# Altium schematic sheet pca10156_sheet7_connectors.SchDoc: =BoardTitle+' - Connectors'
size A3; Organization: Nordic Semiconductor; DocumentNumber: 7; SheetNumber: 7; SheetTotal: 8; CompanyName: Nordic Semiconductor; DocumentSize: A4
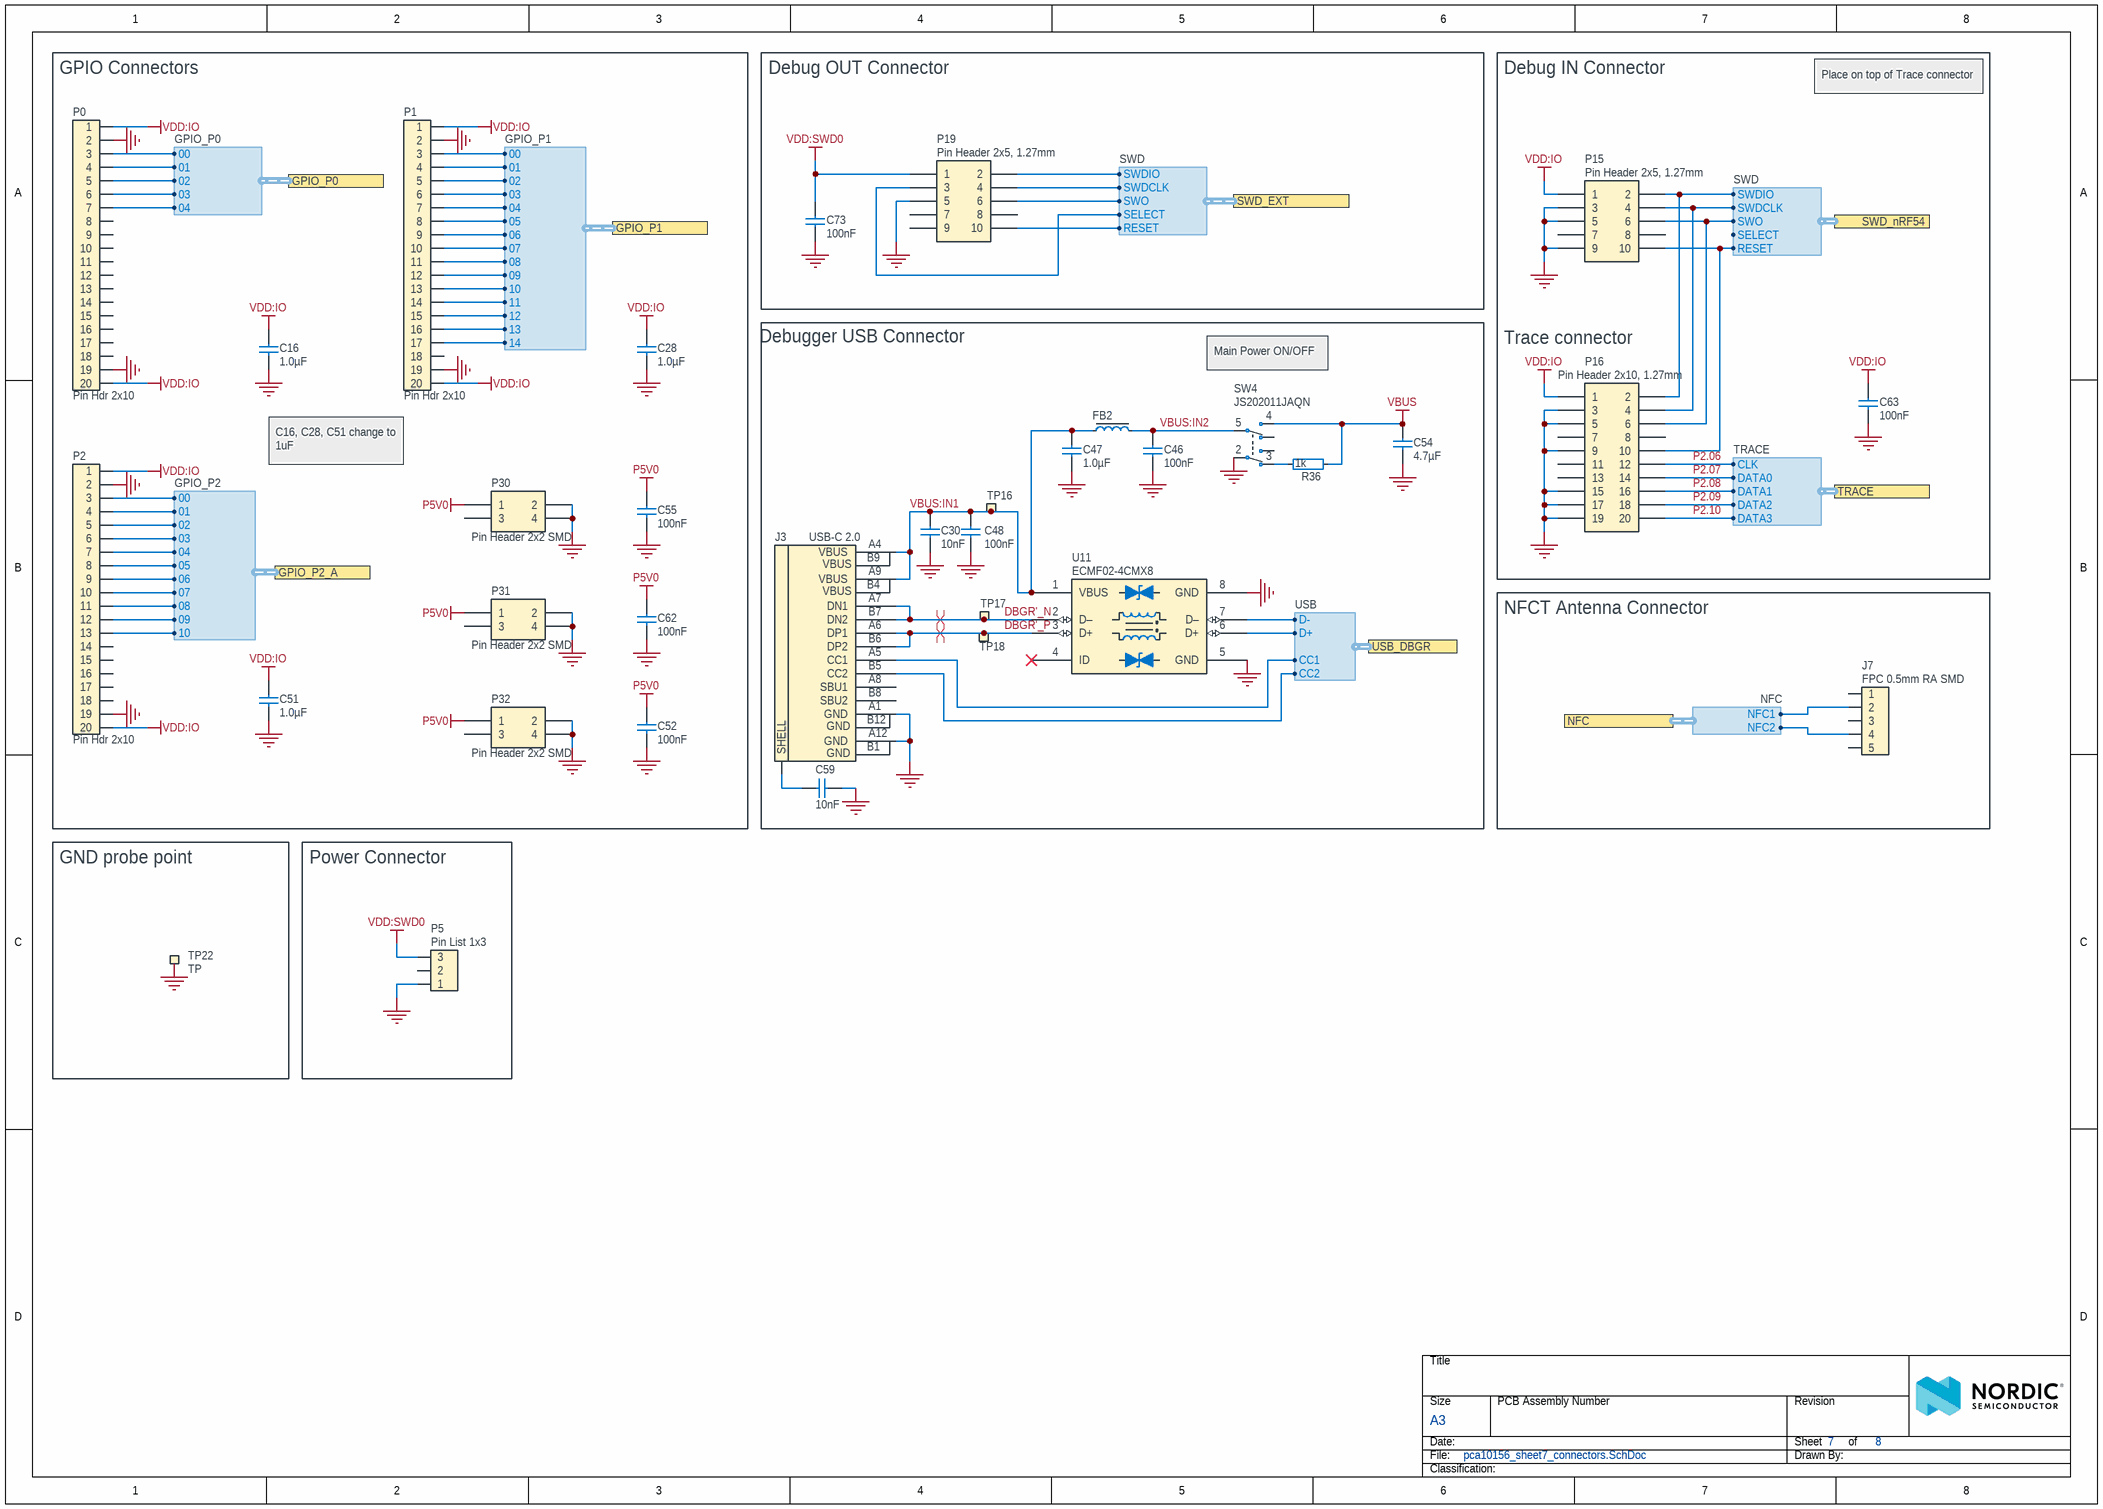
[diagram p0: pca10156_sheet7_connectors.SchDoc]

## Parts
C16  1.0µF  [CAPC1005X04L]
C28  1.0µF  [CAPC1005X04L]
C30  10nF  [CAPC0603X03L_C]
C46  100nF  [CAPC0603X03L_C]
C47  1.0µF  [CAPC1005X04L]
C48  100nF  [CAPC0603X03L_C]
C51  1.0µF  [CAPC1005X04L]
C52  100nF  [CAPC0603X03L_C]
C54  4.7µF  [CAPC1608X06L]
C55  100nF  [CAPC0603X03L_C]
C59  10nF  [CAPC1608X06L]
C62  100nF  [CAPC0603X03L_C]
C63  100nF  [CAPC0603X03L_C]
C73  100nF  [CAPC0603X03L_C]
FB2  120R/0.55A  [INDC1005X04L]  (value not drawn)
J3  USB-C 2.0  [SD-80259-001]
J7  FPC 0.5mm RA SMD  [FPC_05P-0.5mm-RA-SMD]
P0  Pin Hdr 2x10  [HDR_2x10-SMD]
P1  Pin Hdr 2x10  [HDR_2x10-SMD]
P2  Pin Hdr 2x10  [HDR_2x10-SMD]
P5  Pin List 1x3  [LIST_1x3_SMD]
P15  Pin Header 2x5, 1.27mm  [HDR_2x5-SMD-1.27mm-K]
P16  Pin Header 2x10, 1.27mm  [HDR_2x10-SMD-1.27mm-NC]
P19  Pin Header 2x5, 1.27mm  [HDR_2x5-SMD-1.27mm-K]
P30  Pin Header 2x2 SMD  [HDR_2x2-SMD]
P31  Pin Header 2x2 SMD  [HDR_2x2-SMD]
P32  Pin Header 2x2 SMD  [HDR_2x2-SMD]
R36  1k  [RESC0603X03L_C]
SW4  Manufacturer Part Number: JS202011JAQN  [JS102011JAQN]  (hidden comment: Switch)
TP16  Ø1.5mm,SMD  [TP_SMD_D1.5mm]  (value not drawn)  (no BOM)
TP17  Ø1.5mm,SMD  [TP_SMD_D1.5mm]  (value not drawn)  (no BOM)
TP18  Ø1.5mm,SMD  [TP_SMD_D1.5mm]  (value not drawn)  (no BOM)
TP22  TP  [S1751]
U11  ECMF02-4CMX8  [UFDFN50P120X250X55-8N]

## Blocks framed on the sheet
GPIO Connectors: C16 C28 C51 C52 C55 C62 P0-P2 P30-P32
Debug OUT Connector: C73 P19
Debugger USB Connector: C30 C46-C48 C54 C59 FB2 J3 R36 SW4 TP16-TP18 U11
NFCT Antenna Connector: J7
GND probe point: TP22
Power Connector: P5

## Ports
GPIO_P0 (harness GPIO_P0), GPIO_P1 (harness GPIO_P1), GPIO_P2_A (harness GPIO_P2), NFC (harness NFC), SWD_EXT (harness SWD), SWD_nRF54 (harness SWD), TRACE (harness TRACE), USB_DBGR (harness USB)

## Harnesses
USB: D+, D-, CC1, CC2
SWD: SWDIO, SWDCLK, SWO, RESET, SELECT
NFC: NFC2, NFC1
GPIO_P1: 00, 01, 02, 03, 04, 05, 06, 07, 08, 09, 10, 11, 12, 13, 14
GPIO_P2: 00, 01, 02, 03, 04, 05, 06, 07, 08, 09, 10
TRACE: CLK, DATA0, DATA1, DATA3, DATA2
GPIO_P0: 02, 03, 04, 00, 01

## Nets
GND: C16.1 C28.1 C30.2 C46.1 C47.1 C48.1 C51.1 C52.1 C54.2 C55.1 C59.2 C62.1 C63.1 C73.1 J3.A1(GND) J3.A12(GND) P0.2 P0.19 P1.2 P1.19 P2.2 P2.19 P5.1 P15.3 P15.5 P15.9 P16.3 P16.5 P16.9 P16.15 P16.17 P16.19 P19.5 P30.2 P30.4 P31.2 P31.4 P32.2 P32.4 SW4.2(COM-1) TP22.1 U11.5(GND) U11.8(GND)
P5V0: C52.2 C55.2 C62.2 P30.1 P31.1 P32.1
VBUS: C54.1 R36.2 SW4.4(N.O-2)
VDD:IO: C16.2 C28.2 C51.2 C63.2 P0.1 P0.20 P1.1 P1.20 P2.1 P2.20 P15.1 P16.1
VDD:SWD0: C73.2 P5.3 P19.1
DBGR'_N: J3.A7(DN1) J3.B7(DN2) TP17.1 U11.2(D–)
DBGR'_P: J3.A6(DP1) J3.B6(DP2) TP18.1 U11.3(D+)
P2.06: P16.12 ; port TRACE.CLK
P2.07: P16.14 ; port TRACE.DATA0
P2.08: P16.16 ; port TRACE.DATA1
P2.09: P16.18 ; port TRACE.DATA2
P2.10: P16.20 ; port TRACE.DATA3
VBUS:IN1: C30.1 C47.2 C48.2 FB2.1 J3.A4(VBUS) J3.A9(VBUS) TP16.1 U11.1(VBUS)
VBUS:IN2: C46.2 FB2.2 SW4.5(COM-2)
NetC59_1: C59.1 J3.SHLD(SHELL)
NetJ3_A5: J3.A5(CC1) ; port USB_DBGR.CC1
NetJ3_B5: J3.B5(CC2) ; port USB_DBGR.CC2
NetJ7_2: J7.2 ; port NFC.NFC1
NetJ7_4: J7.4 ; port NFC.NFC2
NetP0_3: P0.3 ; port GPIO_P0.00
NetP0_4: P0.4 ; port GPIO_P0.01
NetP0_5: P0.5 ; port GPIO_P0.02
NetP0_6: P0.6 ; port GPIO_P0.03
NetP0_7: P0.7 ; port GPIO_P0.04
NetP1_3: P1.3 ; port GPIO_P1.00
NetP1_4: P1.4 ; port GPIO_P1.01
NetP1_5: P1.5 ; port GPIO_P1.02
NetP1_6: P1.6 ; port GPIO_P1.03
NetP1_7: P1.7 ; port GPIO_P1.04
NetP1_8: P1.8 ; port GPIO_P1.05
NetP1_9: P1.9 ; port GPIO_P1.06
NetP1_10: P1.10 ; port GPIO_P1.07
NetP1_11: P1.11 ; port GPIO_P1.08
NetP1_12: P1.12 ; port GPIO_P1.09
NetP1_13: P1.13 ; port GPIO_P1.10
NetP1_14: P1.14 ; port GPIO_P1.11
NetP1_15: P1.15 ; port GPIO_P1.12
NetP1_16: P1.16 ; port GPIO_P1.13
NetP1_17: P1.17 ; port GPIO_P1.14
NetP2_3: P2.3 ; port GPIO_P2_A.00
NetP2_4: P2.4 ; port GPIO_P2_A.01
NetP2_5: P2.5 ; port GPIO_P2_A.02
NetP2_6: P2.6 ; port GPIO_P2_A.03
NetP2_7: P2.7 ; port GPIO_P2_A.04
NetP2_8: P2.8 ; port GPIO_P2_A.05
NetP2_9: P2.9 ; port GPIO_P2_A.06
NetP2_10: P2.10 ; port GPIO_P2_A.07
NetP2_11: P2.11 ; port GPIO_P2_A.08
NetP2_12: P2.12 ; port GPIO_P2_A.09
NetP2_13: P2.13 ; port GPIO_P2_A.10
NetP15_2: P15.2 P16.2 ; port SWD_nRF54.SWDIO
NetP15_4: P15.4 P16.4 ; port SWD_nRF54.SWDCLK
NetP15_6: P15.6 P16.6 ; port SWD_nRF54.SWO
NetP15_10: P15.10 P16.10 ; port SWD_nRF54.RESET
NetP19_2: P19.2 ; port SWD_EXT.SWDIO
NetP19_3: P19.3 ; port SWD_EXT.SELECT
NetP19_4: P19.4 ; port SWD_EXT.SWDCLK
NetP19_6: P19.6 ; port SWD_EXT.SWO
NetP19_10: P19.10 ; port SWD_EXT.RESET
NetR36_1: R36.1 SW4.3(N.C-1)
NetU11_6: U11.6(D+) ; port USB_DBGR.D+
NetU11_7: U11.7(D–) ; port USB_DBGR.D-

Not connected (* = marked no-connect by the designer): J3 A8(SBU1) B8(SBU2); J7 1 3 5; P0 8 9 10 11 12 13 14 15 16 17 18; P1 18; P2 14 15 16 17 18; P5 2; P15 7 8; P16 7 8 11 13; P19 7 8 9; P30 3; P31 3; P32 3; SW4 1(N.O-1) 6(N.C-2); U11 4(ID)*

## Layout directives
differential pair; differential pair class DBGR; net class DBGR_USB: DBGR'_N, DBGR'_P

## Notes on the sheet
- Debug IN Connector
- Place on top of Trace connector
- Main Power ON/OFF
- (near P16) Trace connector
- C16, C28, C51 change to 1uF

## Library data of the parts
C16 C28 C51 = C0402-1µ0-6.3V-X5R-10%: Capacitor, X5R, ±10%, 6.3V; Manufacturer: N.A.; Part number Norautron: 26207137; Part number NEMS: 100200498; Pad Count: 2; Component Status: Active
C30 = C0201-10n: Capacitor, X7R, ±10%; Manufacturer: N.A.; Part number IPS: 00000003480; Part number Norautron: 26621779; Part number NEMS: 100200067; Note: 10V; Pad Count: 2; Component Status: Active
C46 C48 C52 C55 C62 C63 C73 = C0201-100n: Capacitor, X5R, ±10%; Manufacturer: N.A.; Part number IPS: 00000001248, 00000002505; Part number Norautron: 262071862; Part number NEMS: 100200078; Note: 16V; Pad Count: 2; Component Status: Active
C47 = C0402-1µ0-16V-X5R: Capacitor, Ceramic, X5R, ±10%, 16V; Manufacturer: Murata; Manufacturer Part Number: GRT155R61C105KE01D; Part number NEMS: 100200452; Component Status: Active; Pad Count: 2; Artikkelnr Noca: N.A.
C54 = C0603-4µ7-10V-X7S: Capacitor, X7S, ±10%, 10V; Manufacturer: N.A.; Part number IPS: 00000001779; Part number NEMS: 100200351; Pad Count: 2; Artikkelnr Noca: 20030013; Component Status: Active
C59 = C0603-10n-100V-X7R: Capacitor, X7R, ±10%, 100V; Manufacturer: Murata; Manufacturer Part Number: GCM188R72A103KA37D; Part number NEMS: 100200349; Component Status: Active; Pad Count: 2; Artikkelnr Noca: N.A.
FB2 = FB0402-120R@100M-500mA: Ferrite Bead, 120 Ohm @ 100MHz, 500mA, 250 mOhm Max; Manufacturer: Murata; Manufacturer Part Number: BLM15AG121SN1D; Part number IPS: 00000009954; Part number Norautron: 265230631; Part number NEMS: 100300099; Note: Chip EMIFIL Inductor Type Chip Ferrite Bead; Artikkelnr Noca: 33029317; Pad Count: 2; Component Status: Active
J3 = SD-80259-1021: USB-C Receptacle, 16 Pin, USB 2.0; Manufacturer: Bellweather Electronic Corp.; Part number NEMS: 100500830; Component Status: Active; Pad Count: 16; Note: N.A.; System: Connector
J7 = FPC_05P-0.5mm-RA-SMD: 0.5mm FPC, 5P,Right Angle SMT,Double Contact,H=1.2mm,White, Tin plated; Manufacturer: WCON; Manufacturer Part Number: 5141-05RZDNWR03; Part number NEMS: 100500528; Note: (Replaced 5141-05RZDNWR02); Artikkelnr Noca: N.A.; Pad Count: 7; Component Status: Active; System: Connector
P0-P2 = Pin Header 2x10 SMD, 2.54mm: Pin Header 2x10, 2.54mm (100mil) SMD; Manufacturer: WCON; Manufacturer Part Number: 1125-1210S0M116CR09; Part number NEMS: 100500738; Pad Count: 20; Artikkelnr Noca: N.A.; Component Status: Active; System: Connector
P5 = Pin List 1x3 SMD: Pin List 1x3, 2.54mm (100mil), SMD; Manufacturer: WCON; Manufacturer Part Number: 1125-1103S0M116CR04; Part number Norautron: 26470016; Part number NEMS: 100500306; Note: N.A.; Pad Count: 3; Component Status: Active; System: Connector
P15 P19 = Pin Header 2x5 SMD, 1.27mm, KS: Pin Header 2x5, 1.27mm (50mil), SMD, Keying Shroud; Manufacturer: WCON; Manufacturer Part Number: 3132-10MS0BK00R5; Part number NEMS: 100500261; Note: (Replaced 3132-10MS0BK00R1); Artikkelnr Noca: N.A.; Pad Count: 10; Component Status: Active; System: Connector
P16 = Pin Header 2x10 SMD, 1.27mm, KS, N.C.: Pin Header 2x10, 1.27mm (50mil), SMD, Keying Shroud; Manufacturer: WCON; Manufacturer Part Number: 3132-20MS0BK00R1; Part number NEMS: 100500279; Note: N.A.; Pad Count: 20; Component Status: Active; System: Connector
P30-P32 = Pin Header 2x2 SMD: Pin Header 2x2, SMD, 2.54mm (100mil); Manufacturer: WCON; Manufacturer Part Number: 1125-1202S0M116CR03; Part number NEMS: 100500770; Component Status: Active; Pad Count: 4; Note: N.A.; System: Connector
R36 = R0201-1k0: Resistor, ±1%, 0.05W; Manufacturer: N.A.; Part number IPS: 00000005786; Part number NEMS: 100100043; Component Status: Active; Pad Count: 2; Note: Chip Res 1%
SW4 = Switch-Slide-RA-J-Lead-DPDT-8.5x3.5mm_C&K: SMD slide Switch (ON-ON); Manufacturer: C&K; Part number IPS: 00000007811; Part number NEMS: 101500037; Component Status: Active; Pad Count: 6; Note: N.A.
TP16-TP18 = TP_SMD_Ø1.5MM: 1.5mm circular SMD testpad; Manufacturer: Nordic Semiconductor; Manufacturer Part Number: N.A.; Part number NEMS: 100500477; Pad Count: 1; Component Status: Active
TP22 = TP - S1751-46R: PC TEST POINT TIN SMD L; Manufacturer: Harwin; Part number NEMS: 100500525; Component Status: Active; Pad Count: 1; Note: N.A.
U11 = ECMF02-4CMX8: 2 Line Common mode filter with ESD protection for USB 2.0 interface; Manufacturer: STMicroelectronics; Part number NEMS: 100800034; Component Status: Active; Pad Count: 8; Note: N.A.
